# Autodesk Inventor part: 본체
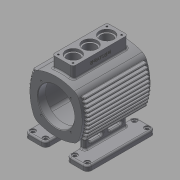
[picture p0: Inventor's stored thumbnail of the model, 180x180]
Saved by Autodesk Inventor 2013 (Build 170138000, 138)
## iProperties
Created: 2015-11
Part Number: 본체
Material: 일반
Document SubType Name: Modeling
Designer: mduedu
Density: 1 g/cm^3
Mass: 569.07 g
Surface Area: 1694.57 cm^2
Volume: 569.07 cm^3
Author: mduedu
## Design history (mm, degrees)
sketch "스케치2"
  geometry: L1 (0, 250)-(0, -250); L2 (250, 0)-(-250, 0); L3 (-50, 50)-(50, 50); L4 (50, 50)-(50, -50); L5 (50, -50)-(-50, -50); L6 (-50, -50)-(-50, 50); A1 r 90 centre (-40, 0) between (40.415, -40.415) and (40.415, 40.415); A2 r 90 centre (40, 0) between (-40.415, 40.415) and (-40.415, -40.415); A3 r 90 centre (0, -40) between (40.415, 40.415) and (-40.415, 40.415); A4 r 90 centre (0, 40) between (-40.415, -40.415) and (40.415, -40.415); 2 further points
  constraints: 12 end point, 8 point on circle, 4 centre point, 4 tangent, 3 perpendicular, 2 horizontal alignment, 2 midpoint, 2 parallel, 2 symmetric about line, 1 coincident, 1 equal radius, 1 horizontal, 1 vertical, 1 vertical alignment, 2 other
  dimensions: "d6" = 500 distance of L1.start L1.end; "d8" = 500 distance of L2.start L2.end; "d9" = 100 distance of L3.end L4.end; "d11" = 90 radius of A3
extrude "돌출1" new body sketch "스케치2" stored distance "d12" = 130; taper "d13" = 0 deg
sketch "스케치3"
  geometry: A1 r 90 centre (40, 0) between (-40.415, 40.415) and (-40.415, -40.415) reference; 2 further points
  constraints: 1 point on circle
fillet "모깎기6" dims "d30" = 15
feature "쉘1" dims "d31" = 15, "d32" = 6, "d33" = 15
sketch "스케치4"
  geometry: L1 (60, -57)-(-60, -57); L2 (-65, 40.415)-(-65, -40.415) reference; L3 (65, -40.415)-(65, 40.415) reference; L4 (-60, -57)-(-60, -45); L5 (60, -57)-(60, -45); L6 (-65, -50)-(65, -50) reference; L7 (-60, -45)-(60, -45); 2 further points
  constraints: 8 end point, 2 parallel, 1 horizontal
  dimensions: "d16" = 5 distance between parallel lines of L7 L6; "d17" = 12 distance of L1.start L5.end; "d23" = 5 distance between parallel lines of L4 L2; "d24" = 5 distance between parallel lines of L5 L3
extrude "돌출2" new body sketch "스케치4" stored distance "d18" = 3; taper "d19" = 0 deg
fillet "모깎기1" dims "d20" = 3
fillet "모깎기4" dims "d25" = 1
sketch "스케치5"
  geometry: C1 r 35 at (0, 0); 1 further point
  constraints: 1 centre point, 1 coincident
  dimensions: "d34" = 70 diameter of C1
extrude "돌출3" cut sketch "스케치5" stored distance "d36" = 3; taper "d37" = 0 deg
feature "결합1"
  node "솔리드2"
fillet "모깎기7" dims "d38" = 1
fillet "모깎기8" dims "d39" = 1
node "작업 평면1"
sketch "스케치6"
  geometry: L1 (-65, -60)-(65, -60); L2 (65, -60)-(65, 60); L3 (65, 60)-(-65, 60); L4 (-65, 60)-(-65, -60); L5 (-65, -60)-(65, 60); L6 (65, -60)-(-65, 60); 1 further point
  constraints: 12 end point, 2 midpoint, 2 parallel, 1 horizontal, 1 perpendicular
  dimensions: "d41" = 120 distance of L3.end L1.start; "d43" = 130 distance of L2.end L3.end
extrude "돌출4" join sketch "스케치6" distance "d44" = 10; taper "d45" = 0 deg
sketch "스케치8"
  geometry: L1 (-60, -70)-(60, -70) reference; L2 (0, -50)-(0, -70); L3 (-30, -44.853)-(-30, -70); L4 (30, -44.853)-(30, -70); L5 (-30, -70)-(30, -70); A1 r 90 centre (0, 40) between (-34.941, -42.941) and (34.941, -42.941) reference; A2 r 90 centre (0, 40) between (-30, -44.853) and (30, -44.853); 1 further point
  constraints: 8 end point, 5 point on circle, 2 perpendicular, 2 symmetric about line, 1 centre point, 1 midpoint, 1 point on line
  dimensions: "d48" = 60 distance between parallel lines of L4 L3
extrude "돌출5" join sketch "스케치8" stored distance "d50" = 80; taper "d51" = 0 deg
sketch "스케치9"
  geometry: L1 (-30, -44.853)-(-30, -70) reference; L2 (30, -70)-(30, -44.853) reference; L3 (-20, -47.75)-(-20, -80); L4 (20, -80)-(20, -47.75); L5 (-48.917, -80)-(48.917, -80) reference; A1 r 90 centre (0, 40) between (-34.941, -42.941) and (34.941, -42.941) reference; 1 further point
  constraints: 4 end point, 2 parallel, 2 point on circle, 2 point on line
  dimensions: "d52" = 10 distance between parallel lines of L2 L4; "d54" = 10 distance between parallel lines of L1 L3 (derived)
extrude "돌출6" cut sketch "스케치9" stored distance "d55" = 80; taper "d56" = 0 deg
fillet "모깎기9" dims "d57" = 8
sketch "스케치10"
  geometry: A1 r 8 centre (-57, 52) between (-57, 60) and (-65, 52) reference; A2 r 8 centre (57, 52) between (65, 52) and (57, 60) reference; A3 r 8 centre (57, 28) between (57, 20) and (65, 28) reference; A4 r 8 centre (-57, 28) between (-65, 28) and (-57, 20) reference; A5 r 8 centre (-57, -28) between (-57, -20) and (-65, -28) reference; A6 r 8 centre (-57, -52) between (-65, -52) and (-57, -60) reference; A7 r 8 centre (57, -52) between (57, -60) and (65, -52) reference; A8 r 8 centre (57, -28) between (65, -28) and (57, -20) reference; 1 further point
hole "구멍1" sketch "스케치10" at (-57, 52), (57, 52), (57, 28), (-57, 28), (-57, -28), (-57, -52), (57, -52), (57, -28) diameter "d58" = 6; stored, may be unused: countersink angle "d62" = 90 deg, drill point angle "d64" = 118 deg; dims "d59" = 6, "d60" = 10, "d61" = 2, "d63" = 8
fillet "모깎기10" dims "d65" = 3
fillet "모깎기11" dims "d66" = 3
fillet "모깎기12" dims "d67" = 3
sketch "스케치11" dims "d72" = 25
  geometry: L1 (65, -50)-(-65, -50) reference; L2 (-80.5, -80)-(80.5, -80) reference; L3 (0, -50)-(0, -80); L4 (-27, -54)-(-10, -54); L5 (-10, -54)-(-10, -62); L6 (-10, -62)-(-27, -62); L7 (-27, -62)-(-27, -54); 3 further points
  constraints: 10 end point, 4 midpoint, 2 parallel, 2 perpendicular, 2 vertical alignment, 1 horizontal, 4 other
  dimensions: "d68" = 8 distance between parallel lines of L6 L4; "d71" = 8 distance from line of point (-27, -58) L1; "d73" = 6 dimension on L3
extrude "돌출7" cut sketch "스케치11" stored distance "d74" = 80; taper "d75" = 0 deg
fillet "모깎기13" dims "d76" = 3
fillet "모깎기14" dims "d78" = 3
sketch "스케치12"
  geometry: L1 (0, 0)-(28.284, 28.284); L2 (0, 0)-(40, 0); A1 r 40 centre (0, 0) between (28.284, 28.284) and (40, 0); 2 further points
  constraints: 4 end point, 2 coincident, 2 point on circle, 1 centre point, 1 horizontal
  dimensions: "d79" = 80 diameter of A1; "d80" = 45 deg angle of L2 L1
hole "구멍2" sketch "스케치12" at (28.284, 28.284) diameter "d82" = 3.242; stored, may be unused: countersink angle "d86" = 90 deg, drill point angle "d88" = 118 deg; dims "d83" = 9, "d84" = 10, "d85" = 2, "d87" = 11
node "작업 평면2"
sketch "스케치13"
  geometry: L1 (-52.5, -20)-(52.5, -20); L2 (52.5, -20)-(52.5, 20); L3 (52.5, 20)-(-52.5, 20); L4 (-52.5, 20)-(-52.5, -20); L5 (-52.5, -20)-(52.5, 20); L6 (52.5, -20)-(-52.5, 20); 1 further point
  constraints: 12 end point, 2 midpoint, 2 parallel, 1 horizontal, 1 perpendicular
  dimensions: "d93" = 105 distance of L2.end L3.end; "d95" = 40 distance of L1.end L2.end
extrude "돌출8" join sketch "스케치13" stored distance "d96" = 80; taper "d97" = 0 deg
fillet "모깎기15" dims "d98" = 5
fillet "모깎기16" dims "d99" = 3
sketch "스케치14"
  geometry: L1 (-52.5, 15)-(-52.5, -15) reference; L2 (52.5, -15)-(52.5, 15) reference; L3 (-52.5, 0)-(52.5, 0); 4 further points
  constraints: 2 end point, 2 midpoint, 2 point on line, 1 coincident
  dimensions: "d100" = 32 distance of point (-32, 0) point (0, 0); "d102" = 32 distance of point (32, 0) point (0, 0) (derived)
hole "구멍3" sketch "스케치14" at (-32, 0), (0, 0), (32, 0) diameter "d103" = 22; stored, may be unused: countersink angle "d107" = 90 deg, drill point angle "d109" = 118 deg; dims "d104" = 8, "d105" = 28, "d106" = 5, "d108" = 10
sketch "스케치15"
  geometry: L1 (46.5, -14)-(-46.5, -14); L2 (-46.5, -14)-(-46.5, 14); L3 (-46.5, 14)-(46.5, 14); L4 (46.5, 14)-(46.5, -14); L5 (46.5, -14)-(-46.5, 14); L6 (-46.5, -14)-(46.5, 14); L7 (47.5, 20)-(-47.5, 20) reference; L8 (-52.5, 15)-(-52.5, -15) reference; 5 further points
  constraints: 12 end point, 4 coincident, 2 midpoint, 2 parallel, 1 horizontal, 1 perpendicular
  dimensions: "d110" = 6 distance between parallel lines of L3 L7; "d111" = 6 distance between parallel lines of L2 L8
hole "구멍4" sketch "스케치15" at (-46.5, 14), (46.5, 14), (46.5, -14), (-46.5, -14) diameter "d112" = 3.242; stored, may be unused: countersink angle "d116" = 90 deg, drill point angle "d118" = 118 deg; dims "d113" = 10, "d114" = 28, "d115" = 5, "d117" = 13
sketch "스케치16"
  geometry: L1 (33.5, 0)-(61.5, 0) reference; L2 (104.5, -150)-(-9.5, -150) reference; L3 (47.5, 0)-(47.5, -150); 2 further points
  constraints: 2 end point, 2 midpoint, 1 point on line, 1 other
  dimensions: "d122" = 11 distance from line of point (47.5, -11) L1
feature "엠보싱2" sketch "스케치16" dims "d16" = 5, "d17" = 12, "d23" = 5, "d24" = 5, "d123" = 0.5, "d124" = 0
chamfer "모따기1" distance "d125" = 1; stored, may be unused: second distance "d126" = 2, angle "d127" = 45 deg
node "솔리드1"
pattern_linear "직사각형 패턴1" dims "d29" = 7
mirror "대칭1"
mirror "대칭2"
pattern_circular "원형 패턴1" dims angle "d90" = 360 deg
mirror "대칭3"
